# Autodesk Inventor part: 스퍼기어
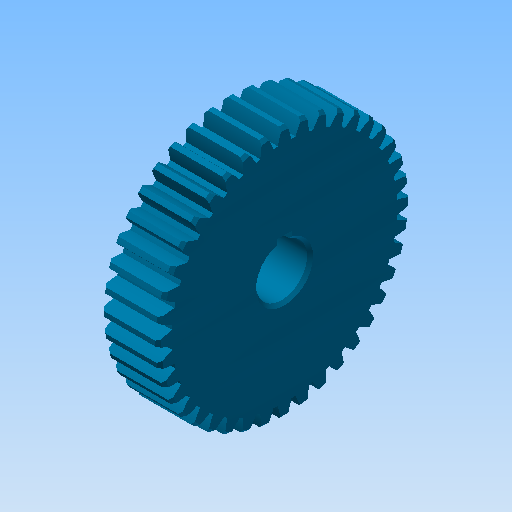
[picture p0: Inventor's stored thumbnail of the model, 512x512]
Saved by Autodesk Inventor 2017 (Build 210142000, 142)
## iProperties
Created: 2018-11
Part Number: 스퍼기어
Material: 알루미늄 6061
Document SubType Name: Modeling
Designer: mduedu
Categories: <?xml version="1.0" encoding="UTF-16"?> <MemberInstance><Categories><FamilyTemplate><FamilyTemplateParameter ValueType="xs:double" Id="1" ObjectReferenceKey="da
Density: 1 g/cm^3
Appearance: Sky Blue Medium
CustomPartVersion: 1
Author: mduedu
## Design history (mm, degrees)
sketch "Sketch1"
  geometry: C1 r 42 at (0, 0)
  constraints: 1 centre point
  dimensions: "d0" = 83.99905 diameter of C1 (= da_da)
extrude "Extrusion1" new body sketch "Sketch1" distance "d1" = 19 (= da_b); taper "d2" = 0 deg
workplane "Work Plane2"
sketch "Sketch2"
  geometry: C1 r 42 at (0, 0) reference; C2 r 40.05 at (0, 0)
  constraints: 1 centre point, 1 coincident
  dimensions: "d3" = 80.10038 diameter of C2 (= da_dw)
feature "피치 지름" sketch "Sketch2" dims "d4" = 10, "d5" = 0
workplane "Work Plane8"
workplane "Work Plane9"
feature "스퍼 기어" dims "da_b" = 19, "da_d" = 80, "da_aw" = 80.10038, "da_da" = 83.99905, "da_df" = 75, "da_dw" = 80.10038, angle "da_beta" = 0 deg, "da_lefttooth" = 0, "da_righttooth" = 0
sketch "스케치3"
  geometry: L1 (-42, 19)-(42, 19) reference; L2 (42, 19)-(42, 0) reference; L3 (42, 0)-(-42, 0) reference; L4 (-42, 0)-(-42, 19) reference; L5 (0, 0)-(0, 19); L6 (42, 0)-(41, 0); L7 (42, 1)-(42, 0); L8 (42, 19)-(41, 19); L9 (42, 18)-(42, 19); L10 (41, 19)-(42, 18); L11 (41, 0)-(42, 1)
  constraints: 14 end point, 2 horizontal, 2 vertical, 1 midpoint
  dimensions: "d49" = 1 distance from line of L8.end L2; "d50" = 1 horizontal distance of L8.end L9.start; "d51" = 1 horizontal distance of L6.end L7.start; "d52" = 1 horizontal distance of L6.end L7.start
revolve "회전1" sketch "스케치3" stored, may be unused: angle "d53" = 90 deg
sketch "스케치4"
  geometry: L1 (-2.5, 8.124)-(2.5, 8.124); L2 (2.5, 8.124)-(2.5, 10.8); L3 (2.5, 10.8)-(-2.5, 10.8); L4 (-2.5, 10.8)-(-2.5, 8.124); A1 r 8.5 centre (0, 0) between (-2.5, 8.124) and (2.5, 8.124); 1 further point
  constraints: 8 end point, 2 parallel, 2 point on circle, 1 centre point, 1 coincident, 1 horizontal, 1 perpendicular
  dimensions: "d54" = 17 diameter of A1; "d56" = 19.3 dimension on A1 L3; "d57" = 5 distance of L2.end L3.end
extrude "돌출2" cut sketch "스케치4" stored distance "d58" = 10; taper "d59" = 0 deg
chamfer "모따기1" distance "d60" = 1; stored, may be unused: second distance "d61" = 2, angle "d62" = 45 deg
sketch "스케치5"
  geometry: C1 r 17.5 at (0, 0); C2 r 28.5 at (0, 0); 1 further point
  constraints: 2 centre point, 2 coincident
  dimensions: "d63" = 35 diameter of C1; "d64" = 57 diameter of C2
extrude "돌출3" cut sketch "스케치5" distance "d65" = 9.5; taper "d66" = 0 deg
fillet "모깎기1" dims "d67" = 3
body "Solid1"
body "Srf1"
node "절단 모서리 투영1"
other parameters: "d16" = 80.10038 (= da_aw), "d17" = 0, "d34" = 4.5 deg (computed from da_z), "d39" = 0, "d41" = 0, "d43" = 80.10038 (= da_aw), "d46" = 80.10038 (= da_aw), "d47" = 0, "d48" = 0
